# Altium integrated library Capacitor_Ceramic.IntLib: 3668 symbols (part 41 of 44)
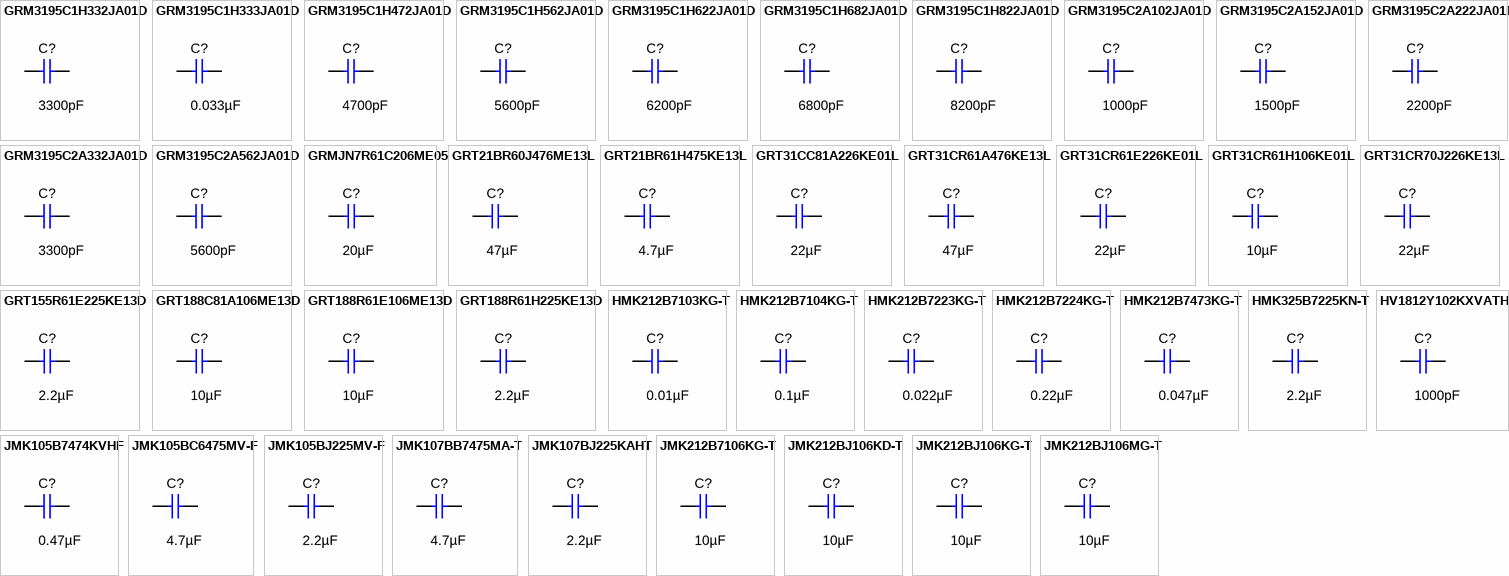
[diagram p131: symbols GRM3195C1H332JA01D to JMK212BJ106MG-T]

## GRM3195C1H682JA01D
designator C?  ValueDisplayed: 6800pF  (hidden comment: GRM3195C1H682JA01D)
CAP, CERM, 6800 pF, 50 V,+/- 5%, C0G/NP0, 1206; Manufacturer: MuRata; Polarized: N; CompType: Capacitor; Value: 6800pF; U/M: EA; Cap_F: 0.0000000068; Tolerance_%: 5; VDC_V: 50; Value2: 50V; TaMin_C: -55; TaMax_C: 125; Cap_Case: 1206; SizeArea_mm2: 5.12; SizeAreaWB_mm2: 10.92; SizeX_mm: 3.2; SizeY_mm: 1.6; SizeZ_mm: 1.35; AEC Category: Q200
signal-integrity model Cap
simulation model Cap
footprint 1206
footprint 1206M
footprint 1206L
pins: 1, 2

## GRM3195C1H822JA01D
designator C?  ValueDisplayed: 8200pF  (hidden comment: GRM3195C1H822JA01D)
CAP, CERM, 8200 pF, 50 V,+/- 5%, C0G/NP0, 1206; Manufacturer: MuRata; Polarized: N; CompType: Capacitor; Value: 8200pF; U/M: EA; Cap_F: 0.0000000082; Tolerance_%: 5; VDC_V: 50; Value2: 50V; TaMin_C: -55; TaMax_C: 125; Cap_Case: 1206; SizeArea_mm2: 5.12; SizeAreaWB_mm2: 10.92; SizeX_mm: 3.2; SizeY_mm: 1.6; SizeZ_mm: 1.35; AEC Category: Q200
signal-integrity model Cap
simulation model Cap
footprint 1206
footprint 1206M
footprint 1206L
pins: 1, 2

## GRM3195C2A102JA01D
designator C?  ValueDisplayed: 1000pF  (hidden comment: GRM3195C2A102JA01D)
CAP, CERM, 1000 pF, 100 V,+/- 5%, C0G/NP0, 1206; Manufacturer: MuRata; Polarized: N; CompType: Capacitor; Value: 1000pF; U/M: EA; Cap_F: 0.000000001; Tolerance_%: 5; VDC_V: 100; Value2: 100V; TaMin_C: -55; TaMax_C: 125; Cap_Case: 1206; SizeArea_mm2: 5.12; SizeAreaWB_mm2: 10.92; SizeX_mm: 3.2; SizeY_mm: 1.6; SizeZ_mm: 1.35; AEC Category: Q200
signal-integrity model Cap
simulation model Cap
footprint 1206
footprint 1206M
footprint 1206L
pins: 1, 2

## GRM3195C2A152JA01D
designator C?  ValueDisplayed: 1500pF  (hidden comment: GRM3195C2A152JA01D)
CAP, CERM, 1500 pF, 100 V,+/- 5%, C0G/NP0, 1206; Manufacturer: MuRata; Polarized: N; CompType: Capacitor; Value: 1500pF; U/M: EA; Cap_F: 0.0000000015; Tolerance_%: 5; VDC_V: 100; Value2: 100V; TaMin_C: -55; TaMax_C: 125; Cap_Case: 1206; SizeArea_mm2: 5.12; SizeAreaWB_mm2: 10.92; SizeX_mm: 3.2; SizeY_mm: 1.6; SizeZ_mm: 1.35; AEC Category: Q200
signal-integrity model Cap
simulation model Cap
footprint 1206
footprint 1206M
footprint 1206L
pins: 1, 2

## GRM3195C2A222JA01D
designator C?  ValueDisplayed: 2200pF  (hidden comment: GRM3195C2A222JA01D)
CAP, CERM, 2200 pF, 100 V,+/- 5%, C0G/NP0, 1206; Manufacturer: MuRata; Polarized: N; CompType: Capacitor; Value: 2200pF; U/M: EA; Cap_F: 0.0000000022; Tolerance_%: 5; VDC_V: 100; Value2: 100V; TaMin_C: -55; TaMax_C: 125; Cap_Case: 1206; SizeArea_mm2: 5.12; SizeAreaWB_mm2: 10.92; SizeX_mm: 3.2; SizeY_mm: 1.6; SizeZ_mm: 1.35; AEC Category: Q200
signal-integrity model Cap
simulation model Cap
footprint 1206
footprint 1206M
footprint 1206L
pins: 1, 2

## GRM3195C2A332JA01D
designator C?  ValueDisplayed: 3300pF  (hidden comment: GRM3195C2A332JA01D)
CAP, CERM, 3300 pF, 100 V,+/- 5%, C0G/NP0, 1206; Manufacturer: MuRata; Polarized: N; CompType: Capacitor; Value: 3300pF; U/M: EA; Cap_F: 0.0000000033; Tolerance_%: 5; ESR_ohm: 0.005; Value1: 0.005 ohm; VDC_V: 100; Value2: 100V; IRMS_A: 0.5; TaMin_C: -55; TaMax_C: 125; Cap_Case: 1206; SizeArea_mm2: 5.12; SizeAreaWB_mm2: 10.92; SizeX_mm: 3.2; SizeY_mm: 1.6; SizeZ_mm: 1.35; AEC Category: Q200
signal-integrity model Cap
simulation model Cap
footprint 1206
footprint 1206M
footprint 1206L
pins: 1, 2

## GRM3195C2A562JA01D
designator C?  ValueDisplayed: 5600pF  (hidden comment: GRM3195C2A562JA01D)
CAP, CERM, 5600 pF, 100 V,+/- 5%, C0G/NP0, 1206; Manufacturer: MuRata; Polarized: N; CompType: Capacitor; Value: 5600pF; U/M: EA; Cap_F: 0.0000000056; Tolerance_%: 5; ESR_ohm: 0.005; Value1: 0.005 ohm; VDC_V: 100; Value2: 100V; IRMS_A: 0.5; TaMin_C: -55; TaMax_C: 125; Cap_Case: 1206; SizeArea_mm2: 5.12; SizeAreaWB_mm2: 10.92; SizeX_mm: 3.2; SizeY_mm: 1.6; SizeZ_mm: 1.35; AEC Category: Q200; Green_Lifecycle: Active; Green_REACh: Passed
signal-integrity model Cap
simulation model Cap
footprint 1206
footprint 1206M
footprint 1206L
pins: 1, 2

## GRMJN7R61C206ME05
designator C?  ValueDisplayed: 20µF  (hidden comment: GRMJN7R61C206ME05)
CAP, CERM, 20 µF, 16 V,+/- 20%, X5R, 0704; Manufacturer: MuRata; Polarized: N; CompType: Capacitor; Value: 20uF; U/M: EA; Cap_F: 2e-005; Tolerance_%: 20; VDC_V: 16; Value2: 16V; TaMin_C: -55; TaMax_C: 85; Cap_Case: 0704; SizeArea_mm2: 1.8; SizeAreaWB_mm2: 5.6; SizeX_mm: 1; SizeZ_mm: 0.8; AEC Category: Q200
signal-integrity model Cap
simulation model Cap
footprint 0704
pins: 1, 2

## GRT21BR60J476ME13L
designator C?  ValueDisplayed: 47µF  (hidden comment: GRT21BR60J476ME13L)
CAP, CERM, 47 µF, 6.3 V,+/- 20%, X5R, AEC-Q200 Grade 3, 0805; Manufacturer: MuRata; Polarized: N; CompType: Capacitor; Value: 47uF; U/M: EA; Cap_F: 0.000047; Tolerance_%: 20; VDC_V: 6.3; Value2: 6.3V; TaMin_C: -55; TaMax_C: 85; Cap_Case: 0805; SizeArea_mm2: 2.5; SizeAreaWB_mm2: 6.75; SizeX_mm: 2; SizeY_mm: 1.25; SizeZ_mm: 1.45; AEC Category: Q200; AEC Qualified: Y; AEC Grade: 3
signal-integrity model Cap
simulation model Cap
footprint 0805_HV
footprint 0805_HV1
footprint 0805
footprint 0805M
footprint 0805L
pins: 1, 2

## GRT21BR61H475KE13L
designator C?  ValueDisplayed: 4.7µF  (hidden comment: GRT21BR61H475KE13L)
CAP, CERM, 4.7 µF, 50 V,+/- 10%, X5R, AEC-Q200 Grade 3, 0805; Manufacturer: MuRata; Polarized: N; CompType: Capacitor; Value: 4.7uF; U/M: EA; Cap_F: 0.0000047; Tolerance_%: 10; VDC_V: 50; Value2: 50V; TaMin_C: -55; TaMax_C: 85; Cap_Case: 0805; SizeArea_mm2: 2.5; SizeAreaWB_mm2: 6.75; SizeX_mm: 2; SizeY_mm: 1.25; SizeZ_mm: 1.45; AEC Category: Q200; AEC Qualified: Y; AEC Grade: 3
signal-integrity model Cap
simulation model Cap
footprint 0805_HV
footprint 0805_HV1
footprint 0805
footprint 0805M
footprint 0805L
pins: 1, 2

## GRT31CC81A226KE01L
designator C?  ValueDisplayed: 22µF  (hidden comment: GRT31CC81A226KE01L)
CAP, CERM, 22 µF, 10 V,+/- 10%, X6S, AEC-Q200 Grade 2, 1206; Manufacturer: MuRata; Polarized: N; CompType: Capacitor; Value: 22uF; U/M: EA; Cap_F: 0.000022; Tolerance_%: 10; Value2: 10V; TaMin_C: -55; TaMax_C: 105; Cap_Case: 1206; SizeArea_mm2: 5.12; SizeAreaWB_mm2: 10.92; SizeX_mm: 3.2; SizeY_mm: 1.6; SizeZ_mm: 1.8; AEC Category: Q200; AEC Qualified: Y; AEC Grade: 2
signal-integrity model Cap
simulation model Cap
footprint 1206_180
footprint 1206_180M
footprint 1206_180L
pins: 1, 2

## GRT31CR61A476KE13L
designator C?  ValueDisplayed: 47µF  (hidden comment: GRT31CR61A476KE13L)
CAP, CERM, 47 µF, 10 V,+/- 10%, X5R, AEC-Q200 Grade 1, 1206; Manufacturer: MuRata; Polarized: N; CompType: Capacitor; Value: 47uF; U/M: EA; Cap_F: 0.000047; Tolerance_%: 10; Value2: 10V; TaMin_C: -55; TaMax_C: 85; Cap_Case: 1206; SizeArea_mm2: 5.12; SizeAreaWB_mm2: 10.92; SizeX_mm: 3.2; SizeY_mm: 1.6; SizeZ_mm: 1.8; AEC Category: Q200; AEC Qualified: Y; AEC Grade: 1
signal-integrity model Cap
simulation model Cap
footprint 1206_180
footprint 1206_180M
footprint 1206_180L
pins: 1, 2

## GRT31CR61E226KE01L
designator C?  ValueDisplayed: 22µF  (hidden comment: GRT31CR61E226KE01L)
CAP, CERM, 22 µF, 25 V,+/- 10%, X5R, AEC-Q200 Grade 3, 1206; Manufacturer: MuRata; Polarized: N; CompType: Capacitor; Value: 22uF; U/M: EA; Cap_F: 0.000022; Tolerance_%: 10; VDC_V: 25; Value2: 25V; TaMin_C: -55; TaMax_C: 85; Cap_Case: 1206; SizeArea_mm2: 5.12; SizeAreaWB_mm2: 10.92; SizeX_mm: 3.2; SizeY_mm: 1.6; SizeZ_mm: 1.8; AEC Category: Q200; AEC Qualified: Y; AEC Grade: 3
signal-integrity model Cap
simulation model Cap
footprint 1206_180
footprint 1206_180M
footprint 1206_180L
pins: 1, 2

## GRT31CR61H106KE01L
designator C?  ValueDisplayed: 10µF  (hidden comment: GRT31CR61H106KE01L)
CAP, CERM, 10 µF, 50 V,+/- 10%, X5R, AEC-Q200 Grade 1, 1206; Manufacturer: MuRata; Polarized: N; CompType: Capacitor; Value: 10uF; U/M: EA; Cap_F: 0.00001; Tolerance_%: 10; VDC_V: 50; Value2: 50V; TaMin_C: -55; TaMax_C: 85; Cap_Case: 1206; SizeArea_mm2: 5.12; SizeAreaWB_mm2: 10.92; SizeX_mm: 3.2; SizeY_mm: 1.6; SizeZ_mm: 1.8; AEC Category: Q200; AEC Qualified: Y; AEC Grade: 1
signal-integrity model Cap
simulation model Cap
footprint 1206_180
footprint 1206_180M
footprint 1206_180L
pins: 1, 2

## GRT31CR70J226KE13L
designator C?  ValueDisplayed: 22µF  (hidden comment: GRT31CR70J226KE13L)
CAP, CERM, 22 µF, 6.3 V,+/- 10%, X7R, AEC-Q200 Grade 1, 1206; Manufacturer: MuRata; Polarized: N; CompType: Capacitor; Value: 22uF; U/M: EA; Cap_F: 0.000022; Tolerance_%: 10; VDC_V: 6.3; Value2: 6.3V; TaMin_C: -55; TaMax_C: 125; Cap_Case: 1206; SizeArea_mm2: 5.12; SizeAreaWB_mm2: 10.92; SizeX_mm: 3.2; SizeY_mm: 1.6; SizeZ_mm: 1.8; AEC Category: Q200; AEC Qualified: Y; AEC Grade: 1
signal-integrity model Cap
simulation model Cap
footprint 1206_180
footprint 1206_180M
footprint 1206_180L
pins: 1, 2

## GRT155R61E225KE13D
designator C?  ValueDisplayed: 2.2µF  (hidden comment: GRT155R61E225KE13D)
CAP, CERM, 2.2 µF, 25 V,+/- 10%, X5R, AEC-Q200 Grade 3, 0402; Manufacturer: MuRata; Polarized: N; CompType: Capacitor; Value: 2.2uF; U/M: EA; Cap_F: 0.0000022; Tolerance_%: 10; VDC_V: 25; Value2: 25V; TaMin_C: -55; TaMax_C: 85; Cap_Case: 0402; SizeArea_mm2: 0.5; SizeAreaWB_mm2: 3; SizeX_mm: 1; SizeZ_mm: 0.6; AEC Category: Q200; AEC Qualified: Y
signal-integrity model Cap
simulation model Cap
footprint 0402
footprint 0402M
footprint 0402L
footprint 0402S
pins: 1, 2

## GRT188C81A106ME13D
designator C?  ValueDisplayed: 10µF  (hidden comment: GRT188C81A106ME13D)
CAP, CERM, 10 µF, 10 V,+/- 20%, X6S, AEC-Q200 Grade 2, 0603; Manufacturer: MuRata; Polarized: N; CompType: Capacitor; Value: 10uF; U/M: EA; Cap_F: 0.00001; Tolerance_%: 20; VDC_V: 10; Value2: 10V; TaMin_C: -55; TaMax_C: 105; Cap_Case: 0603; SizeArea_mm2: 1.28; SizeAreaWB_mm2: 4.68; SizeX_mm: 1.6; SizeY_mm: 0.8; SizeZ_mm: 1; AEC Category: Q200; AEC Qualified: Y; AEC Grade: 2; Green_Lifecycle: Active; Green_REACh: Passed
signal-integrity model Cap
simulation model Cap
footprint 0603
footprint 0603M
footprint 0603L
footprint 0603_HV
footprint 0603S
pins: 1, 2

## GRT188R61E106ME13D
designator C?  ValueDisplayed: 10µF  (hidden comment: GRT188R61E106ME13D)
CAP, CERM, 10 µF, 25 V,+/- 20%, X5R, 0603; Manufacturer: MuRata; Polarized: N; CompType: Capacitor; Value: 10uF; U/M: EA; Cap_F: 0.00001; Tolerance_%: 20; VDC_V: 25; Value2: 25V; TaMin_C: -55; TaMax_C: 85; Cap_Case: 0603; SizeArea_mm2: 1.28; SizeAreaWB_mm2: 4.68; SizeX_mm: 1.6; SizeY_mm: 0.8; SizeZ_mm: 1; AEC Category: Q200
signal-integrity model Cap
simulation model Cap
footprint 0603
footprint 0603M
footprint 0603L
footprint 0603_HV
footprint 0603S
pins: 1, 2

## GRT188R61H225KE13D
designator C?  ValueDisplayed: 2.2µF  (hidden comment: GRT188R61H225KE13D)
CAP, CERM, 2.2 µF, 50 V,+/- 10%, X5R, AEC-Q200 Grade 3, 0603; Manufacturer: MuRata; Polarized: N; CompType: Capacitor; Value: 2.2uF; U/M: EA; Cap_F: 0.0000022; Tolerance_%: 10; VDC_V: 50; Value2: 50V; TaMin_C: -55; TaMax_C: 85; Cap_Case: 0603; SizeArea_mm2: 1.28; SizeAreaWB_mm2: 4.68; SizeX_mm: 1.6; SizeY_mm: 0.8; SizeZ_mm: 1; AEC Category: Q200; AEC Qualified: Y; AEC Grade: 3
signal-integrity model Cap
simulation model Cap
footprint 0603
footprint 0603M
footprint 0603L
footprint 0603_HV
footprint 0603S
pins: 1, 2

## HMK212B7103KG-T
designator C?  ValueDisplayed: 0.01µF  (hidden comment: HMK212B7103KG-T)
CAP, CERM, 0.01 µF, 100 V,+/- 10%, X7R, 0805; Manufacturer: Taiyo Yuden; Polarized: N; CompType: Capacitor; Value: 0.01uF; U/M: EA; Cap_F: 0.00000001; Tolerance_%: 10; VDC_V: 100; Value2: 100V; TaMin_C: -55; TaMax_C: 125; Cap_Case: 0805; SizeArea_mm2: 2.5; SizeAreaWB_mm2: 6.75; SizeX_mm: 2; SizeY_mm: 1.25; SizeZ_mm: 1.45; AEC Category: Q200
signal-integrity model Cap
simulation model Cap
footprint 0805_HV
footprint 0805_HV1
footprint 0805
footprint 0805M
footprint 0805L
pins: 1, 2

## HMK212B7104KG-T
designator C?  ValueDisplayed: 0.1µF  (hidden comment: HMK212B7104KG-T)
CAP, CERM, 0.1 µF, 100 V,+/- 10%, X7R, 0805; Manufacturer: Taiyo Yuden; Polarized: N; CompType: Capacitor; Value: 0.1uF; U/M: EA; Cap_F: 0.0000001; Tolerance_%: 10; VDC_V: 100; Value2: 100V; TaMin_C: -55; TaMax_C: 125; Cap_Case: 0805; SizeArea_mm2: 2.5; SizeAreaWB_mm2: 6.75; SizeX_mm: 2; SizeY_mm: 1.25; SizeZ_mm: 1.45; AEC Category: Q200; Green_Lifecycle: Active; Green_REACh: Passed
signal-integrity model Cap
simulation model Cap
footprint 0805_HV
footprint 0805_HV1
footprint 0805
footprint 0805M
footprint 0805L
pins: 1, 2

## HMK212B7223KG-T
designator C?  ValueDisplayed: 0.022µF  (hidden comment: HMK212B7223KG-T)
CAP, CERM, 0.022 µF, 100 V,+/- 10%, X7R, 0805; Manufacturer: Taiyo Yuden; Polarized: N; CompType: Capacitor; Value: 0.022uF; U/M: EA; Cap_F: 0.000000022; Tolerance_%: 10; VDC_V: 100; Value2: 100V; TaMin_C: -55; TaMax_C: 125; Cap_Case: 0805; SizeArea_mm2: 2.5; SizeAreaWB_mm2: 6.75; SizeX_mm: 2; SizeY_mm: 1.25; SizeZ_mm: 1.45; AEC Category: Q200
signal-integrity model Cap
simulation model Cap
footprint 0805_HV
footprint 0805_HV1
footprint 0805
footprint 0805M
footprint 0805L
pins: 1, 2

## HMK212B7224KG-T
designator C?  ValueDisplayed: 0.22µF  (hidden comment: HMK212B7224KG-T)
CAP, CERM, 0.22 µF, 100 V,+/- 10%, X7R, 0805; Manufacturer: Taiyo Yuden; Polarized: N; CompType: Capacitor; Value: 0.22uF; U/M: EA; Cap_F: 0.00000022; Tolerance_%: 10; VDC_V: 100; Value2: 100V; TaMin_C: -55; TaMax_C: 125; Cap_Case: 0805; SizeArea_mm2: 2.5; SizeAreaWB_mm2: 6.75; SizeX_mm: 2; SizeY_mm: 1.25; SizeZ_mm: 1.45; AEC Category: Q200
signal-integrity model Cap
simulation model Cap
footprint 0805_HV
footprint 0805_HV1
footprint 0805
footprint 0805M
footprint 0805L
pins: 1, 2

## HMK212B7473KG-T
designator C?  ValueDisplayed: 0.047µF  (hidden comment: HMK212B7473KG-T)
CAP, CERM, 0.047 µF, 100 V,+/- 10%, X7R, 0805; Manufacturer: Taiyo Yuden; Polarized: N; CompType: Capacitor; Value: 0.047uF; U/M: EA; Cap_F: 0.000000047; Tolerance_%: 10; VDC_V: 100; Value2: 100V; TaMin_C: -55; TaMax_C: 125; Cap_Case: 0805; SizeArea_mm2: 2.5; SizeAreaWB_mm2: 6.75; SizeX_mm: 2; SizeY_mm: 1.25; SizeZ_mm: 1.45; AEC Category: Q200
signal-integrity model Cap
simulation model Cap
footprint 0805_HV
footprint 0805_HV1
footprint 0805
footprint 0805M
footprint 0805L
pins: 1, 2

## HMK325B7225KN-T
designator C?  ValueDisplayed: 2.2µF  (hidden comment: HMK325B7225KN-T)
CAP, CERM, 2.2 µF, 100 V,+/- 10%, X7R, 1210; Manufacturer: Taiyo Yuden; Polarized: N; CompType: Capacitor; Value: 2.2uF; U/M: EA; Cap_F: 0.0000022; Tolerance_%: 10; VDC_V: 100; Value2: 100V; TaMin_C: -55; TaMax_C: 125; Cap_Case: 1210; SizeArea_mm2: 8; SizeAreaWB_mm2: 14.7; SizeX_mm: 3.2; SizeY_mm: 2.5; SizeZ_mm: 1.35; AEC Category: Q200; Green_Lifecycle: Not Set; Green_REACh: Incomplete
signal-integrity model Cap
simulation model Cap
footprint 1210
footprint 1210M
footprint 1210L
pins: 1, 2

## HV1812Y102KXVATHV
designator C?  ValueDisplayed: 1000pF  (hidden comment: HV1812Y102KXVATHV)
CAP, CERM, 1000 pF, 4000 V,+/- 10%, X7R, 1812; Manufacturer: Vishay-Vitramon; Polarized: N; CompType: Capacitor; Value: 1000pF; U/M: EA; Cap_F: 0.000000001; Tolerance_%: 10; VDC_V: 4000; Value2: 4000V; TaMin_C: -55; TaMax_C: 125; Cap_Case: 1812; SizeArea_mm2: 14.4; SizeAreaWB_mm2: 23.1; SizeX_mm: 4.5; SizeY_mm: 3.2; SizeZ_mm: 2.8; AEC Category: Q200
signal-integrity model Cap
simulation model Cap
footprint 1812_280
footprint 1812_280M
footprint 1812_280L
pins: 1, 2

## JMK105B7474KVHF
designator C?  ValueDisplayed: 0.47µF  (hidden comment: JMK105B7474KVHF)
CAP, CERM, 0.47 µF, 6.3 V,+/- 10%, X7R, 0402; Manufacturer: Taiyo Yuden; Polarized: N; CompType: Capacitor; Value: 0.47uF; U/M: EA; Cap_F: 0.00000047; Tolerance_%: 10; VDC_V: 6.3; Value2: 6.3V; TaMin_C: -55; TaMax_C: 125; Cap_Case: 0402; SizeArea_mm2: 0.5; SizeAreaWB_mm2: 3; SizeX_mm: 1; SizeZ_mm: 0.6; AEC Category: Q200
signal-integrity model Cap
simulation model Cap
footprint 0402
footprint 0402M
footprint 0402L
footprint 0402S
pins: 1, 2

## JMK105BC6475MV-F
designator C?  ValueDisplayed: 4.7µF  (hidden comment: JMK105BC6475MV-F)
CAP, CERM, 4.7 µF, 6.3 V,+/- 20%, X6S, 0402; Manufacturer: Taiyo Yuden; Polarized: N; CompType: Capacitor; Value: 4.7uF; U/M: EA; Cap_F: 0.0000047; Tolerance_%: 20; VDC_V: 6.3; Value2: 6.3V; TaMin_C: -55; TaMax_C: 105; Cap_Case: 0402; SizeArea_mm2: 0.5; SizeAreaWB_mm2: 3; SizeX_mm: 1; SizeZ_mm: 0.6; AEC Category: Q200
signal-integrity model Cap
simulation model Cap
footprint 0402
footprint 0402M
footprint 0402L
footprint 0402S
pins: 1, 2

## JMK105BJ225MV-F
designator C?  ValueDisplayed: 2.2µF  (hidden comment: JMK105BJ225MV-F)
CAP, CERM, 2.2 µF, 6.3 V,+/- 20%, X5R, 0402; Manufacturer: Taiyo Yuden; Polarized: N; CompType: Capacitor; Value: 2.2uF; U/M: EA; Cap_F: 0.0000022; Tolerance_%: 20; ESR_ohm: 0.00152; Value1: 0.00152 ohm; VDC_V: 6.3; Value2: 6.3V; TaMin_C: -55; TaMax_C: 125; Cap_Case: 0402; SizeArea_mm2: 0.5; SizeAreaWB_mm2: 3; SizeX_mm: 1; SizeZ_mm: 0.6; AEC Category: Q200; Green_Lifecycle: Active; Green_REACh: Passed
signal-integrity model Cap
simulation model Cap
footprint 0402
footprint 0402M
footprint 0402L
footprint 0402S
pins: 1, 2

## JMK107BB7475MA-T
designator C?  ValueDisplayed: 4.7µF  (hidden comment: JMK107BB7475MA-T)
CAP, CERM, 4.7 µF, 6.3 V,+/- 10%, X7R, 0603; Manufacturer: Taiyo Yuden; Polarized: N; CompType: Capacitor; Value: 4.7uF; U/M: EA; Cap_F: 0.0000047; Tolerance_%: 10; VDC_V: 6.3; Value2: 6.3V; TaMin_C: -55; TaMax_C: 125; Cap_Case: 0603; SizeArea_mm2: 1.28; SizeAreaWB_mm2: 4.68; SizeX_mm: 1.6; SizeY_mm: 0.8; SizeZ_mm: 1; AEC Category: Q200
signal-integrity model Cap
simulation model Cap
footprint 0603
footprint 0603M
footprint 0603L
footprint 0603_HV
footprint 0603S
pins: 1, 2

## JMK107BJ225KAHT
designator C?  ValueDisplayed: 2.2µF  (hidden comment: JMK107BJ225KAHT)
CAP, CERM, 2.2 µF, 6.3 V,+/- 10%, X5R, 0603; Manufacturer: Taiyo Yuden; Polarized: N; CompType: Capacitor; Value: 2.2uF; U/M: EA; Cap_F: 0.0000022; Tolerance_%: 10; VDC_V: 6.3; Value2: 6.3V; TaMin_C: -55; TaMax_C: 85; Cap_Case: 0603; SizeArea_mm2: 1.28; SizeAreaWB_mm2: 4.68; SizeX_mm: 1.6; SizeY_mm: 0.8; SizeZ_mm: 1; AEC Category: Q200; Green_Lifecycle: Active; Green_REACh: Passed
signal-integrity model Cap
simulation model Cap
footprint 0603
footprint 0603M
footprint 0603L
footprint 0603_HV
footprint 0603S
pins: 1, 2

## JMK212B7106KG-T
designator C?  ValueDisplayed: 10µF  (hidden comment: JMK212B7106KG-T)
CAP, CERM, 10 µF, 6.3 V,+/- 10%, X7R, 0805; Manufacturer: Taiyo Yuden; Polarized: N; CompType: Capacitor; Value: 10uF; U/M: EA; Cap_F: 0.00001; Tolerance_%: 10; VDC_V: 6.3; Value2: 6.3V; TaMin_C: -55; TaMax_C: 125; Cap_Case: 0805; SizeArea_mm2: 2.5; SizeAreaWB_mm2: 6.75; SizeX_mm: 2; SizeY_mm: 1.25; SizeZ_mm: 1.45; AEC Category: Q200; Green_Lifecycle: Not Set; Green_REACh: Incomplete
signal-integrity model Cap
simulation model Cap
footprint 0805_HV
footprint 0805_HV1
footprint 0805
footprint 0805M
footprint 0805L
pins: 1, 2

## JMK212BJ106KD-T
designator C?  ValueDisplayed: 10µF  (hidden comment: JMK212BJ106KD-T)
CAP, CERM, 10 µF, 6.3 V,+/- 10%, X5R, 0805; Manufacturer: Taiyo Yuden; Polarized: N; CompType: Capacitor; Value: 10uF; U/M: EA; Cap_F: 0.00001; Tolerance_%: 10; ESR_ohm: 0.002; Value1: 0.002 ohm; VDC_V: 6.3; Value2: 6.3V; TaMin_C: -55; TaMax_C: 85; Cap_Case: 0805; SizeArea_mm2: 2.5; SizeAreaWB_mm2: 6.75; SizeX_mm: 2; SizeY_mm: 1.25; SizeZ_mm: 1.45; AEC Category: Q200
signal-integrity model Cap
simulation model Cap
footprint 0805_HV
footprint 0805_HV1
footprint 0805
footprint 0805M
footprint 0805L
pins: 1, 2

## JMK212BJ106KG-T
designator C?  ValueDisplayed: 10µF  (hidden comment: JMK212BJ106KG-T)
CAP, CERM, 10 µF, 6.3 V,+/- 10%, X5R, 0805; Manufacturer: Taiyo Yuden; Polarized: N; CompType: Capacitor; Value: 10uF; U/M: EA; Cap_F: 0.00001; Tolerance_%: 10; ESR_ohm: 0.002; Value1: 0.002 ohm; VDC_V: 6.3; Value2: 6.3V; TaMin_C: -55; TaMax_C: 85; Cap_Case: 0805; SizeArea_mm2: 2.5; SizeAreaWB_mm2: 6.75; SizeX_mm: 2; SizeY_mm: 1.25; SizeZ_mm: 1.45; AEC Category: Q200
signal-integrity model Cap
simulation model Cap
footprint 0805_HV
footprint 0805_HV1
footprint 0805
footprint 0805M
footprint 0805L
pins: 1, 2

## JMK212BJ106MG-T
designator C?  ValueDisplayed: 10µF  (hidden comment: JMK212BJ106MG-T)
CAP, CERM, 10 µF, 6.3 V,+/- 20%, X5R, 0805; Manufacturer: Taiyo Yuden; Polarized: N; CompType: Capacitor; Value: 10uF; U/M: EA; Cap_F: 0.00001; Tolerance_%: 20; VDC_V: 6.3; Value2: 6.3V; TaMin_C: -55; TaMax_C: 85; Cap_Case: 0805; SizeArea_mm2: 2.5; SizeAreaWB_mm2: 6.75; SizeX_mm: 2; SizeY_mm: 1.25; SizeZ_mm: 1.45; AEC Category: Q200
signal-integrity model Cap
simulation model Cap
footprint 0805_HV
footprint 0805_HV1
footprint 0805
footprint 0805M
footprint 0805L
pins: 1, 2

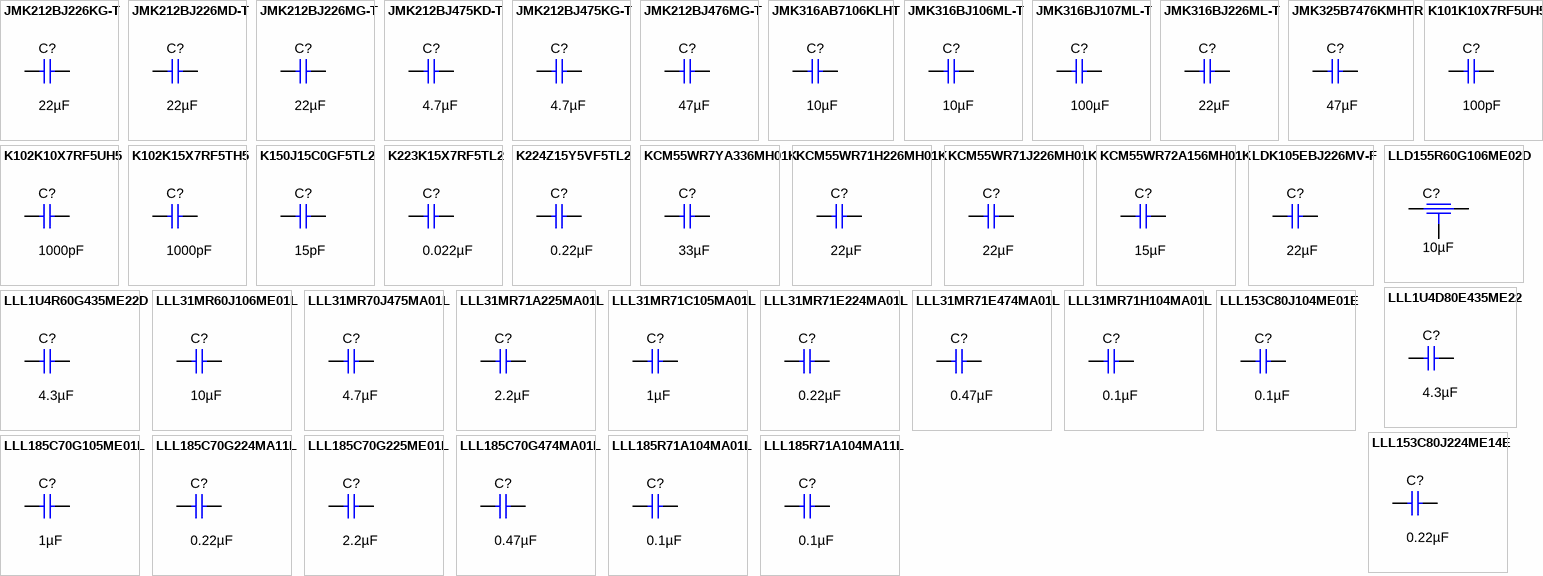
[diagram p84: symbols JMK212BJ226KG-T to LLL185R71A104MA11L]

## JMK212BJ226KG-T
designator C?  ValueDisplayed: 22µF  (hidden comment: JMK212BJ226KG-T)
CAP, CERM, 22 µF, 6.3 V,+/- 10%, X5R, 0805; Manufacturer: Taiyo Yuden; Polarized: N; CompType: Capacitor; Value: 22uF; U/M: EA; Cap_F: 0.000022; Tolerance_%: 10; ESR_ohm: 0.002; Value1: 0.002 ohm; VDC_V: 6.3; Value2: 6.3V; TaMin_C: -55; TaMax_C: 85; Cap_Case: 0805; SizeArea_mm2: 2.5; SizeAreaWB_mm2: 6.75; SizeX_mm: 2; SizeY_mm: 1.25; SizeZ_mm: 1.45; AEC Category: Q200; Green_Lifecycle: Not Set; Green_REACh: Incomplete
signal-integrity model Cap
simulation model Cap
footprint 0805_HV
footprint 0805_HV1
footprint 0805
footprint 0805M
footprint 0805L
pins: 1, 2

## JMK212BJ226MD-T
designator C?  ValueDisplayed: 22µF  (hidden comment: JMK212BJ226MD-T)
CAP, CERM, 22 µF, 6.3 V,+/- 20%, X5R, 0805; Manufacturer: Taiyo Yuden; Polarized: N; CompType: Capacitor; Value: 22uF; U/M: EA; Cap_F: 0.000022; Tolerance_%: 20; VDC_V: 6.3; Value2: 6.3V; TaMin_C: -55; TaMax_C: 85; Cap_Case: 0805; SizeArea_mm2: 2.5; SizeAreaWB_mm2: 6.75; SizeX_mm: 2; SizeY_mm: 1.25; SizeZ_mm: 1.45; AEC Category: Q200
signal-integrity model Cap
simulation model Cap
footprint 0805_HV
footprint 0805_HV1
footprint 0805
footprint 0805M
footprint 0805L
pins: 1, 2

## JMK212BJ226MG-T
designator C?  ValueDisplayed: 22µF  (hidden comment: JMK212BJ226MG-T)
CAP, CERM, 22 µF, 6.3 V,+/- 20%, X5R, 0805; Manufacturer: Taiyo Yuden; Polarized: N; CompType: Capacitor; Value: 22uF; U/M: EA; Cap_F: 0.000022; Tolerance_%: 20; VDC_V: 6.3; Value2: 6.3V; TaMin_C: -55; TaMax_C: 85; Cap_Case: 0805; SizeArea_mm2: 2.5; SizeAreaWB_mm2: 6.75; SizeX_mm: 2; SizeY_mm: 1.25; SizeZ_mm: 1.45; AEC Category: Q200; Green_Lifecycle: Not Set; Green_REACh: Incomplete
signal-integrity model Cap
simulation model Cap
footprint 0805_HV
footprint 0805_HV1
footprint 0805
footprint 0805M
footprint 0805L
pins: 1, 2

## JMK212BJ475KD-T
designator C?  ValueDisplayed: 4.7µF  (hidden comment: JMK212BJ475KD-T)
CAP, CERM, 4.7 µF, 6.3 V,+/- 10%, X5R, 0805; Manufacturer: Taiyo Yuden; Polarized: N; CompType: Capacitor; Value: 4.7uF; U/M: EA; Cap_F: 0.0000047; Tolerance_%: 10; ESR_ohm: 0.004; Value1: 0.004 ohm; VDC_V: 6.3; Value2: 6.3V; TaMin_C: -55; TaMax_C: 85; Cap_Case: 0805; SizeArea_mm2: 2.5; SizeAreaWB_mm2: 6.75; SizeX_mm: 2; SizeY_mm: 1.25; SizeZ_mm: 1.45; AEC Category: Q200
signal-integrity model Cap
simulation model Cap
footprint 0805_HV
footprint 0805_HV1
footprint 0805
footprint 0805M
footprint 0805L
pins: 1, 2

## JMK212BJ475KG-T
designator C?  ValueDisplayed: 4.7µF  (hidden comment: JMK212BJ475KG-T)
CAP, CERM, 4.7 µF, 6.3 V,+/- 10%, X5R, 0805; Manufacturer: Taiyo Yuden; Polarized: N; CompType: Capacitor; Value: 4.7uF; U/M: EA; Cap_F: 0.0000047; Tolerance_%: 10; ESR_ohm: 0.004; Value1: 0.004 ohm; VDC_V: 6.3; Value2: 6.3V; TaMin_C: -55; TaMax_C: 85; Cap_Case: 0805; SizeArea_mm2: 2.5; SizeAreaWB_mm2: 6.75; SizeX_mm: 2; SizeY_mm: 1.25; SizeZ_mm: 1.45; AEC Category: Q200; Green_Lifecycle: Not Set; Green_REACh: Incomplete
signal-integrity model Cap
simulation model Cap
footprint 0805_HV
footprint 0805_HV1
footprint 0805
footprint 0805M
footprint 0805L
pins: 1, 2

## JMK212BJ476MG-T
designator C?  ValueDisplayed: 47µF  (hidden comment: JMK212BJ476MG-T)
CAP, CERM, 47 µF, 6.3 V,+/- 20%, X5R, 0805; Manufacturer: Taiyo Yuden; Polarized: N; CompType: Capacitor; Value: 47uF; U/M: EA; Cap_F: 0.000047; Tolerance_%: 20; VDC_V: 6.3; Value2: 6.3V; TaMin_C: -55; TaMax_C: 85; Cap_Case: 0805; SizeArea_mm2: 2.5; SizeAreaWB_mm2: 6.75; SizeX_mm: 2; SizeY_mm: 1.25; SizeZ_mm: 1.45; AEC Category: Q200; Green_Lifecycle: Not Set; Green_REACh: Incomplete
signal-integrity model Cap
simulation model Cap
footprint 0805_HV
footprint 0805_HV1
footprint 0805
footprint 0805M
footprint 0805L
pins: 1, 2

## JMK316AB7106KLHT
designator C?  ValueDisplayed: 10µF  (hidden comment: JMK316AB7106KLHT)
CAP, CERM, 10 µF, 6.3 V,+/- 10%, X7R, AEC-Q200 Grade 1, 1206; Manufacturer: Taiyo Yuden; Polarized: N; CompType: Capacitor; Value: 10uF; U/M: EA; Cap_F: 0.00001; Tolerance_%: 10; VDC_V: 6.3; Value2: 6.3V; TaMin_C: -55; TaMax_C: 125; Cap_Case: 1206; SizeArea_mm2: 5.12; SizeAreaWB_mm2: 10.92; SizeX_mm: 3.2; SizeY_mm: 1.6; SizeZ_mm: 1.8; AEC Category: Q200; AEC Qualified: Y; AEC Grade: 1
signal-integrity model Cap
simulation model Cap
footprint 1206_180
footprint 1206_180M
footprint 1206_180L
pins: 1, 2

## JMK316BJ106ML-T
designator C?  ValueDisplayed: 10µF  (hidden comment: JMK316BJ106ML-T)
CAP, CERM, 10 µF, 6.3 V,+/- 20%, X5R, 1206; Manufacturer: Taiyo Yuden; Polarized: N; CompType: Capacitor; Value: 10uF; U/M: EA; Cap_F: 0.00001; Tolerance_%: 20; ESR_ohm: 0.008; Value1: 0.008 ohm; VDC_V: 6.3; Value2: 6.3V; TaMin_C: -55; TaMax_C: 125; Cap_Case: 1206; SizeArea_mm2: 5.12; SizeAreaWB_mm2: 10.92; SizeX_mm: 3.2; SizeY_mm: 1.6; SizeZ_mm: 1.35; AEC Category: Q200
signal-integrity model Cap
simulation model Cap
footprint 1206
footprint 1206M
footprint 1206L
pins: 1, 2

## JMK316BJ107ML-T
designator C?  ValueDisplayed: 100µF  (hidden comment: JMK316BJ107ML-T)
CAP, CERM, 100 µF, 6.3 V,+/- 20%, X5R, 1206; Manufacturer: Taiyo Yuden; Polarized: N; CompType: Capacitor; Value: 100uF; U/M: EA; Cap_F: 0.0001; Tolerance_%: 20; VDC_V: 6.3; Value2: 6.3V; TaMin_C: -55; TaMax_C: 85; Cap_Case: 1206; SizeArea_mm2: 5.12; SizeAreaWB_mm2: 10.92; SizeX_mm: 3.2; SizeY_mm: 1.6; SizeZ_mm: 1.35; AEC Category: Q200
signal-integrity model Cap
simulation model Cap
footprint 1206
footprint 1206M
footprint 1206L
pins: 1, 2

## JMK316BJ226ML-T
designator C?  ValueDisplayed: 22µF  (hidden comment: JMK316BJ226ML-T)
CAP, CERM, 22 µF, 6.3 V,+/- 20%, X5R, 1206; Manufacturer: Taiyo Yuden; Polarized: N; CompType: Capacitor; Value: 22uF; U/M: EA; Cap_F: 0.000022; Tolerance_%: 20; ESR_ohm: 0.012; Value1: 0.012 ohm; VDC_V: 6.3; Value2: 6.3V; TaMin_C: -55; TaMax_C: 125; Cap_Case: 1206; SizeArea_mm2: 5.12; SizeAreaWB_mm2: 10.92; SizeX_mm: 3.2; SizeY_mm: 1.6; SizeZ_mm: 1.35; AEC Category: Q200
signal-integrity model Cap
simulation model Cap
footprint 1206
footprint 1206M
footprint 1206L
pins: 1, 2

## JMK325B7476KMHTR
designator C?  ValueDisplayed: 47µF  (hidden comment: JMK325B7476KMHTR)
CAP, CERM, 47 µF, 6.3 V,+/- 10%, X7R, AEC-Q200 Grade 1, 1210; Manufacturer: Taiyo Yuden; Polarized: N; CompType: Capacitor; Value: 47uF; U/M: EA; Cap_F: 0.000047; Tolerance_%: 10; VDC_V: 6.3; Value2: 6.3V; TaMin_C: -55; TaMax_C: 125; Cap_Case: 1210; SizeArea_mm2: 8; SizeAreaWB_mm2: 14.7; SizeX_mm: 3.2; SizeY_mm: 2.5; SizeZ_mm: 2.7; AEC Category: Q200; AEC Qualified: Y; AEC Grade: 1
signal-integrity model Cap
simulation model Cap
footprint 1210_270
footprint 1210_270M
footprint 1210_270L
pins: 1, 2

## K101K10X7RF5UH5
designator C?  ValueDisplayed: 100pF  (hidden comment: K101K10X7RF5UH5)
CAP, CERM, 100 pF, 50 V,+/- 10%, X7R, 3.6x6.2x2.3mm; Manufacturer: Vishay-Bccomponents; Polarized: N; CompType: Capacitor; Value: 100pF; U/M: EA; Cap_F: 0.0000000001; Tolerance_%: 10; VDC_V: 50; Value2: 50V; TaMin_C: -55; TaMax_C: 125; SizeArea_mm2: 8.28; SizeAreaWB_mm2: 15.18; SizeX_mm: 3.6; SizeY_mm: 2.3; SizeZ_mm: 6.2; AEC Category: Q200
signal-integrity model Cap
simulation model Cap
footprint K_10_H5
pins: 1, 2

## K102K10X7RF5UH5
designator C?  ValueDisplayed: 1000pF  (hidden comment: K102K10X7RF5UH5)
CAP, CERM, 1000 pF, 50 V,+/- 10%, X7R, 3.6x2.3mm; Manufacturer: Vishay-Bccomponents; Polarized: N; CompType: Capacitor; Value: 1000pF; U/M: EA; Cap_F: 0.000000001; Tolerance_%: 10; VDC_V: 50; Value2: 50V; TaMin_C: -55; TaMax_C: 125; Cap_Case: 3.6x2.3x6.2mm; SizeArea_mm2: 8.28; SizeAreaWB_mm2: 15.18; SizeX_mm: 3.6; SizeY_mm: 2.3; SizeZ_mm: 6.2; AEC Category: Q200
signal-integrity model Cap
simulation model Cap
footprint K10_360x230x620
pins: 1, 2

## K102K15X7RF5TH5
designator C?  ValueDisplayed: 1000pF  (hidden comment: K102K15X7RF5TH5)
CAP, CERM, 1000 pF, 50 V,+/- 10%, X7R, 4.0x6.6x2.6mm; Manufacturer: Vishay-Bccomponents; Polarized: N; CompType: Capacitor; Value: 1000pF; U/M: EA; Cap_F: 0.000000001; Tolerance_%: 10; VDC_V: 50; Value2: 50V; TaMin_C: -55; TaMax_C: 125; Cap_Case: 4x6.6x2.6mm; SizeAreaWB_mm2: 17.5; SizeX_mm: 4; SizeY_mm: 2.5; SizeZ_mm: 6.6; AEC Category: Q200
signal-integrity model Cap
simulation model Cap
footprint K_15_H5
pins: 1, 2

## K150J15C0GF5TL2
designator C?  ValueDisplayed: 15pF  (hidden comment: K150J15C0GF5TL2)
CAP, CERM, 15 pF, 50 V,+/- 5%, C0G/NP0, 4.0x5.6x2.6mm; Manufacturer: Vishay-Bccomponents; Polarized: N; CompType: Capacitor; Value: 15pF; U/M: EA; Cap_F: 0.000000000015; Tolerance_%: 5; VDC_V: 50; Value2: 50V; TaMin_C: -55; TaMax_C: 125; Cap_Case: K_15_L2; SizeArea_mm2: 10; SizeAreaWB_mm2: 17.5; SizeX_mm: 4; SizeY_mm: 2.5; SizeZ_mm: 5.6; AEC Category: Q200
signal-integrity model Cap
simulation model Cap
footprint K_15_L2
pins: 1, 2

## K223K15X7RF5TL2
designator C?  ValueDisplayed: 0.022µF  (hidden comment: K223K15X7RF5TL2)
CAP, CERM, 0.022 µF, 50 V,+/- 10%, X7R, 4.0x5.6x2.6mm; Manufacturer: Vishay-Bccomponents; Polarized: N; CompType: Capacitor; Value: 0.022uF; U/M: EA; Cap_F: 0.000000022; Tolerance_%: 10; VDC_V: 50; Value2: 50V; TaMin_C: -55; TaMax_C: 125; Cap_Case: K_15_L2; SizeAreaWB_mm2: 17.5; SizeX_mm: 4; SizeY_mm: 2.5; SizeZ_mm: 5.6; AEC Category: Q200
signal-integrity model Cap
simulation model Cap
footprint K_15_L2
pins: 1, 2

## K224Z15Y5VF5TL2
designator C?  ValueDisplayed: 0.22µF  (hidden comment: K224Z15Y5VF5TL2)
CAP, CERM, 0.22 µF, 50 V,+/- 80%, Y5V, 4.0x5.6x2.6mm; Manufacturer: Vishay-Bccomponents; Polarized: N; CompType: Capacitor; Value: 0.22uF; U/M: EA; Cap_F: 0.00000022; Tolerance_%: 80; VDC_V: 50; Value2: 50V; TaMin_C: -30; TaMax_C: 85; Cap_Case: K_15_L2; SizeArea_mm2: 10; SizeAreaWB_mm2: 17.5; SizeX_mm: 4; SizeY_mm: 2.5; SizeZ_mm: 5.6; AEC Category: Q200
signal-integrity model Cap
simulation model Cap
footprint K_15_L2
pins: 1, 2

## KCM55WR7YA336MH01K
designator C?  ValueDisplayed: 33µF  (hidden comment: KCM55WR7YA336MH01K)
CAP, CERM, 33 µF, 35 V,+/- 20%, X7R, Stacked 2220; Manufacturer: MuRata; Polarized: N; CompType: Capacitor; Value: 33uF; U/M: EA; Cap_F: 0.000033; Tolerance_%: 20; VDC_V: 35; Value2: 35V; TaMin_C: -55; TaMax_C: 125; Cap_Case: 2220; SizeArea_mm2: 32.33; SizeAreaWB_mm2: 59.13; SizeX_mm: 6.1; SizeY_mm: 5.3; SizeZ_mm: 6.7; AEC Category: Q200
signal-integrity model Cap
simulation model Cap
footprint KCM55W
pins: 1, 2

## KCM55WR71H226MH01K
designator C?  ValueDisplayed: 22µF  (hidden comment: KCM55WR71H226MH01K)
CAP, CERM, 22 µF, 50 V,+/- 20%, X7R, Stacked 2220; Manufacturer: MuRata; Polarized: N; CompType: Capacitor; Value: 22uF; U/M: EA; Cap_F: 0.000022; Tolerance_%: 20; VDC_V: 50; Value2: 50V; TaMin_C: -55; TaMax_C: 125; Cap_Case: 2220; SizeArea_mm2: 32.33; SizeAreaWB_mm2: 59.13; SizeX_mm: 6.1; SizeY_mm: 5.3; SizeZ_mm: 6.7; AEC Category: Q200
signal-integrity model Cap
simulation model Cap
footprint KCM55W
pins: 1, 2

## KCM55WR71J226MH01K
designator C?  ValueDisplayed: 22µF  (hidden comment: KCM55WR71J226MH01K)
CAP, CERM, 22 µF, 63 V,+/- 20%, X7R, Stacked 2220; Manufacturer: MuRata; Polarized: N; CompType: Capacitor; Value: 22uF; U/M: EA; Cap_F: 0.000022; Tolerance_%: 20; VDC_V: 63; Value2: 63V; TaMin_C: -55; TaMax_C: 125; Cap_Case: 2220; SizeArea_mm2: 32.33; SizeAreaWB_mm2: 59.13; SizeX_mm: 6.1; SizeY_mm: 5.3; SizeZ_mm: 6.7; AEC Category: Q200
signal-integrity model Cap
simulation model Cap
footprint KCM55W
pins: 1, 2

## KCM55WR72A156MH01K
designator C?  ValueDisplayed: 15µF  (hidden comment: KCM55WR72A156MH01K)
CAP, CERM, 15 µF, 100 V,+/- 20%, X7R, Stacked 2220; Manufacturer: MuRata; Polarized: N; CompType: Capacitor; Value: 15uF; U/M: EA; Cap_F: 0.000015; Tolerance_%: 20; VDC_V: 100; Value2: 100V; TaMin_C: -55; TaMax_C: 125; Cap_Case: 2220; SizeArea_mm2: 32.33; SizeAreaWB_mm2: 59.13; SizeX_mm: 6.1; SizeY_mm: 5.3; SizeZ_mm: 6.7; AEC Category: Q200
signal-integrity model Cap
simulation model Cap
footprint KCM55W
pins: 1, 2

## LDK105EBJ226MV-F
designator C?  ValueDisplayed: 22µF  (hidden comment: LDK105EBJ226MV-F)
CAP, CERM, 22 µF, 10 V,+/- 20%, X5R, 0402; Manufacturer: Taiyo Yuden; Polarized: N; CompType: Capacitor; Value: 22uF; U/M: EA; Cap_F: 0.000022; Tolerance_%: 20; VDC_V: 10; Value2: 10V; TaMin_C: -55; TaMax_C: 105; Cap_Case: 0402; SizeArea_mm2: 0.5; SizeAreaWB_mm2: 3; SizeX_mm: 1; SizeZ_mm: 0.8; AEC Category: Q200
signal-integrity model Cap
simulation model Cap
footprint 0402_080
footprint 0402_080S
pins: 1, 2

## LLD155R60G106ME02D
designator C?  ValueDisplayed: 10µF  (hidden comment: LLD155R60G106ME02D)
CAP, CERM, 10 µF, 4 V,+/- 20%, X5R, 0402; Manufacturer: MuRata; SymbolCreator: a0411947; CompType: Capacitor; U/M: EA; Cap_F: 0.00001; Value: 10uF; Tolerance_%: 20; VDC_V: 4; Value2: 4V; TaMin_C: -55; TaMax_C: 85; Polarized: N; Cap_Case: 0402; SizeArea_mm2: 0.5; SizeAreaWB_mm2: 3; SizeX_mm: 1; SizeZ_mm: 0.7; AEC Category: Q200
footprint LLD155
pins: 1, 2, 3

## LLL1U4D80E435ME22
designator C?  ValueDisplayed: 4.3µF  (hidden comment: LLL1U4D80E435ME22)
CAP, CERM, 4.3 µF, 2.5 V,+/- 20%, X6T, SMD, 2-Leads, Body 0.6x1mm, Height 0.45mm; Manufacturer: MuRata; Polarized: N; CompType: Capacitor; Value: 4.3uF; U/M: EA; Cap_F: 4.3e-006; Tolerance_%: 20; ESR_ohm: 0.0029; Value1: 0.0029 ohm; VDC_V: 2.5; Value2: 2.5V; TaMin_C: -55; TaMax_C: 105; Cap_Case: 02404; SizeArea_mm2: 0.6; SizeAreaWB_mm2: 3.2; SizeY_mm: 1; SizeZ_mm: 0.45; AEC Category: Q200
signal-integrity model Cap
simulation model Cap
footprint 02404
pins: 1, 2

## LLL1U4R60G435ME22D
designator C?  ValueDisplayed: 4.3µF  (hidden comment: LLL1U4R60G435ME22D)
CAP, CERM, 4.3 µF, 4 V,+/- 20%, X5R, SMD, 2-Leads, Body 0.6x1mm, Height 0.45mm; Manufacturer: MuRata; Polarized: N; CompType: Capacitor; Value: 4.3uF; U/M: EA; Cap_F: 4.3e-006; Tolerance_%: 20; VDC_V: 4; Value2: 4V; TaMin_C: -55; TaMax_C: 85; Cap_Case: 02404; SizeArea_mm2: 0.6; SizeAreaWB_mm2: 3.2; SizeY_mm: 1; SizeZ_mm: 0.45; AEC Category: Q200
signal-integrity model Cap
simulation model Cap
footprint 02404
pins: 1, 2

## LLL31MR60J106ME01L
designator C?  ValueDisplayed: 10µF  (hidden comment: LLL31MR60J106ME01L)
CAP, CERM, 10 µF, 6.3 V,+/- 20%, X5R, 0612; Manufacturer: MuRata; Polarized: N; CompType: Capacitor; Value: 10uF; U/M: EA; Cap_F: 0.00001; Tolerance_%: 20; VDC_V: 6.3; Value2: 6.3V; TaMin_C: -55; TaMax_C: 85; Cap_Case: 0612; SizeArea_mm2: 5.12; SizeAreaWB_mm2: 10.92; SizeX_mm: 1.6; SizeY_mm: 3.2; SizeZ_mm: 0.85; AEC Category: Q200
signal-integrity model Cap
simulation model Cap
footprint 0612
pins: 1, 2

## LLL31MR70J475MA01L
designator C?  ValueDisplayed: 4.7µF  (hidden comment: LLL31MR70J475MA01L)
CAP, CERM, 4.7 µF, 6.3 V,+/- 20%, X7R, 0612; Manufacturer: MuRata; Polarized: N; CompType: Capacitor; Value: 4.7uF; U/M: EA; Cap_F: 0.0000047; Tolerance_%: 20; VDC_V: 6.3; Value2: 6.3V; TaMin_C: -55; TaMax_C: 125; Cap_Case: 0612; SizeArea_mm2: 5.12; SizeAreaWB_mm2: 10.92; SizeX_mm: 1.6; SizeY_mm: 3.2; SizeZ_mm: 0.85; AEC Category: Q200
signal-integrity model Cap
simulation model Cap
footprint 0612
pins: 1, 2

## LLL31MR71A225MA01L
designator C?  ValueDisplayed: 2.2µF  (hidden comment: LLL31MR71A225MA01L)
CAP, CERM, 2.2 µF, 10 V,+/- 20%, X7R, 0612; Manufacturer: MuRata; Polarized: N; CompType: Capacitor; Value: 2.2uF; U/M: EA; Cap_F: 0.0000022; Tolerance_%: 20; VDC_V: 10; Value2: 10V; TaMin_C: -55; TaMax_C: 125; Cap_Case: 0612; SizeArea_mm2: 5.12; SizeAreaWB_mm2: 10.92; SizeX_mm: 1.6; SizeY_mm: 3.2; SizeZ_mm: 0.85; AEC Category: Q200
signal-integrity model Cap
simulation model Cap
footprint 0612
pins: 1, 2

## LLL31MR71C105MA01L
designator C?  ValueDisplayed: 1µF  (hidden comment: LLL31MR71C105MA01L)
CAP, CERM, 1 µF, 16 V,+/- 20%, X7R, 0612; Manufacturer: MuRata; Polarized: N; CompType: Capacitor; Value: 1uF; U/M: EA; Cap_F: 0.000001; Tolerance_%: 20; VDC_V: 16; Value2: 16V; TaMin_C: -55; TaMax_C: 125; Cap_Case: 0612; SizeArea_mm2: 5.12; SizeAreaWB_mm2: 10.92; SizeX_mm: 1.6; SizeY_mm: 3.2; SizeZ_mm: 0.85; AEC Category: Q200
signal-integrity model Cap
simulation model Cap
footprint 0612
pins: 1, 2

## LLL31MR71E224MA01L
designator C?  ValueDisplayed: 0.22µF  (hidden comment: LLL31MR71E224MA01L)
CAP, CERM, 0.22 µF, 25 V,+/- 20%, X7R, 0612; Manufacturer: MuRata; Polarized: N; CompType: Capacitor; Value: 0.22uF; U/M: EA; Cap_F: 0.00000022; Tolerance_%: 20; VDC_V: 25; Value2: 25V; TaMin_C: -55; TaMax_C: 125; Cap_Case: 0612; SizeArea_mm2: 5.12; SizeAreaWB_mm2: 10.92; SizeX_mm: 1.6; SizeY_mm: 3.2; SizeZ_mm: 0.85; AEC Category: Q200
signal-integrity model Cap
simulation model Cap
footprint 0612
pins: 1, 2

## LLL31MR71E474MA01L
designator C?  ValueDisplayed: 0.47µF  (hidden comment: LLL31MR71E474MA01L)
CAP, CERM, 0.47 µF, 25 V,+/- 20%, X7R, 0612; Manufacturer: MuRata; Polarized: N; CompType: Capacitor; Value: 0.47uF; U/M: EA; Cap_F: 0.00000047; Tolerance_%: 20; VDC_V: 25; Value2: 25V; TaMin_C: -55; TaMax_C: 125; Cap_Case: 0612; SizeArea_mm2: 5.12; SizeAreaWB_mm2: 10.92; SizeX_mm: 1.6; SizeY_mm: 3.2; SizeZ_mm: 0.85; AEC Category: Q200
signal-integrity model Cap
simulation model Cap
footprint 0612
pins: 1, 2

## LLL31MR71H104MA01L
designator C?  ValueDisplayed: 0.1µF  (hidden comment: LLL31MR71H104MA01L)
CAP, CERM, 0.1 µF, 50 V,+/- 20%, X7R, 0612; Manufacturer: MuRata; Polarized: N; CompType: Capacitor; Value: 0.1uF; U/M: EA; Cap_F: 0.0000001; Tolerance_%: 20; VDC_V: 50; Value2: 50V; TaMin_C: -55; TaMax_C: 125; Cap_Case: 0612; SizeArea_mm2: 5.12; SizeAreaWB_mm2: 10.92; SizeX_mm: 1.6; SizeY_mm: 3.2; SizeZ_mm: 0.85; AEC Category: Q200
signal-integrity model Cap
simulation model Cap
footprint 0612
pins: 1, 2

## LLL153C80J104ME01E
designator C?  ValueDisplayed: 0.1µF  (hidden comment: LLL153C80J104ME01E)
CAP, CERM, 0.1 µF, 6.3 V,+/- 20%, X6S, SMD, Body 1x0.52mm; Manufacturer: MuRata; Polarized: N; CompType: Capacitor; Value: 0.1uF; U/M: EA; Cap_F: 0.0000001; Tolerance_%: 20; VDC_V: 6.3; Value2: 6.3V; TaMin_C: -55; TaMax_C: 105; Cap_Case: 0204; SizeArea_mm2: 0.5; SizeAreaWB_mm2: 3; SizeY_mm: 1; SizeZ_mm: 0.35; AEC Category: Q200
signal-integrity model Cap
simulation model Cap
footprint 0204
pins: 1, 2

## LLL153C80J224ME14E
designator C?  ValueDisplayed: 0.22µF  (hidden comment: LLL153C80J224ME14E)
CAP, CERM, 0.22 µF, 6.3 V,+/- 20%, X6S, SMD, Body 1x0.52mm; Manufacturer: MuRata; Polarized: N; CompType: Capacitor; Value: 0.22uF; U/M: EA; Cap_F: 0.00000022; Tolerance_%: 20; VDC_V: 6.3; Value2: 6.3V; TaMin_C: -55; TaMax_C: 105; Cap_Case: 0204; SizeArea_mm2: 0.5; SizeAreaWB_mm2: 3; SizeY_mm: 1; SizeZ_mm: 0.35; AEC Category: Q200
signal-integrity model Cap
simulation model Cap
footprint 0204
pins: 1, 2

## LLL185C70G105ME01L
designator C?  ValueDisplayed: 1µF  (hidden comment: LLL185C70G105ME01L)
CAP, CERM, 1 µF, 4 V,+/- 20%, X7S, 0306; Manufacturer: MuRata; Polarized: N; CompType: Capacitor; Value: 1uF; U/M: EA; Cap_F: 0.000001; Tolerance_%: 20; VDC_V: 4; Value2: 4V; TaMin_C: -55; TaMax_C: 125; Cap_Case: 0306; SizeArea_mm2: 1.28; SizeAreaWB_mm2: 4.68; SizeX_mm: 0.8; SizeY_mm: 1.6; SizeZ_mm: 0.6; AEC Category: Q200
signal-integrity model Cap
simulation model Cap
footprint 0306
pins: 1, 2

## LLL185C70G224MA11L
designator C?  ValueDisplayed: 0.22µF  (hidden comment: LLL185C70G224MA11L)
CAP, CERM, 0.22 µF, 4 V,+/- 20%, X7S, 0306; Manufacturer: MuRata; Polarized: N; CompType: Capacitor; Value: 0.22uF; U/M: EA; Cap_F: 0.00000022; Tolerance_%: 20; VDC_V: 4; Value2: 4V; TaMin_C: -55; TaMax_C: 125; Cap_Case: 0306; SizeArea_mm2: 1.28; SizeAreaWB_mm2: 4.68; SizeX_mm: 0.8; SizeY_mm: 1.6; SizeZ_mm: 0.6; AEC Category: Q200
signal-integrity model Cap
simulation model Cap
footprint 0306
pins: 1, 2

## LLL185C70G225ME01L
designator C?  ValueDisplayed: 2.2µF  (hidden comment: LLL185C70G225ME01L)
CAP, CERM, 2.2 µF, 4 V,+/- 20%, X7S, 0306; Manufacturer: MuRata; Polarized: N; CompType: Capacitor; Value: 2.2uF; U/M: EA; Cap_F: 0.0000022; Tolerance_%: 20; VDC_V: 4; Value2: 4V; TaMin_C: -55; TaMax_C: 125; Cap_Case: 0306; SizeArea_mm2: 1.28; SizeAreaWB_mm2: 4.68; SizeX_mm: 0.8; SizeY_mm: 1.6; SizeZ_mm: 0.6; AEC Category: Q200
signal-integrity model Cap
simulation model Cap
footprint 0306
pins: 1, 2

## LLL185C70G474MA01L
designator C?  ValueDisplayed: 0.47µF  (hidden comment: LLL185C70G474MA01L)
CAP, CERM, 0.47 µF, 4 V,+/- 20%, X7S, 0306; Manufacturer: MuRata; Polarized: N; CompType: Capacitor; Value: 0.47uF; U/M: EA; Cap_F: 0.00000047; Tolerance_%: 20; VDC_V: 4; Value2: 4V; TaMin_C: -55; TaMax_C: 125; Cap_Case: 0306; SizeArea_mm2: 1.28; SizeAreaWB_mm2: 4.68; SizeX_mm: 0.8; SizeY_mm: 1.6; SizeZ_mm: 0.6; AEC Category: Q200
signal-integrity model Cap
simulation model Cap
footprint 0306
pins: 1, 2

## LLL185R71A104MA01L
designator C?  ValueDisplayed: 0.1µF  (hidden comment: LLL185R71A104MA01L)
CAP, CERM, 0.1 µF, 10 V,+/- 20%, X7R, 0306; Manufacturer: MuRata; Polarized: N; CompType: Capacitor; Value: 0.1uF; U/M: EA; Cap_F: 0.0000001; Tolerance_%: 20; VDC_V: 10; Value2: 10V; TaMin_C: -55; TaMax_C: 125; Cap_Case: 0306; SizeArea_mm2: 1.28; SizeAreaWB_mm2: 4.68; SizeX_mm: 0.8; SizeY_mm: 1.6; SizeZ_mm: 0.6; AEC Category: Q200
signal-integrity model Cap
simulation model Cap
footprint 0306
pins: 1, 2

## LLL185R71A104MA11L
designator C?  ValueDisplayed: 0.1µF  (hidden comment: LLL185R71A104MA11L)
CAP, CERM, 0.1 µF, 10 V,+/- 20%, X7R, 0306; Manufacturer: MuRata; Polarized: N; CompType: Capacitor; Value: 0.1uF; U/M: EA; Cap_F: 0.0000001; Tolerance_%: 20; VDC_V: 10; Value2: 10V; TaMin_C: -55; TaMax_C: 125; Cap_Case: 0306; SizeArea_mm2: 1.28; SizeAreaWB_mm2: 4.68; SizeX_mm: 0.8; SizeY_mm: 1.6; SizeZ_mm: 0.6; AEC Category: Q200
signal-integrity model Cap
simulation model Cap
footprint 0306
pins: 1, 2

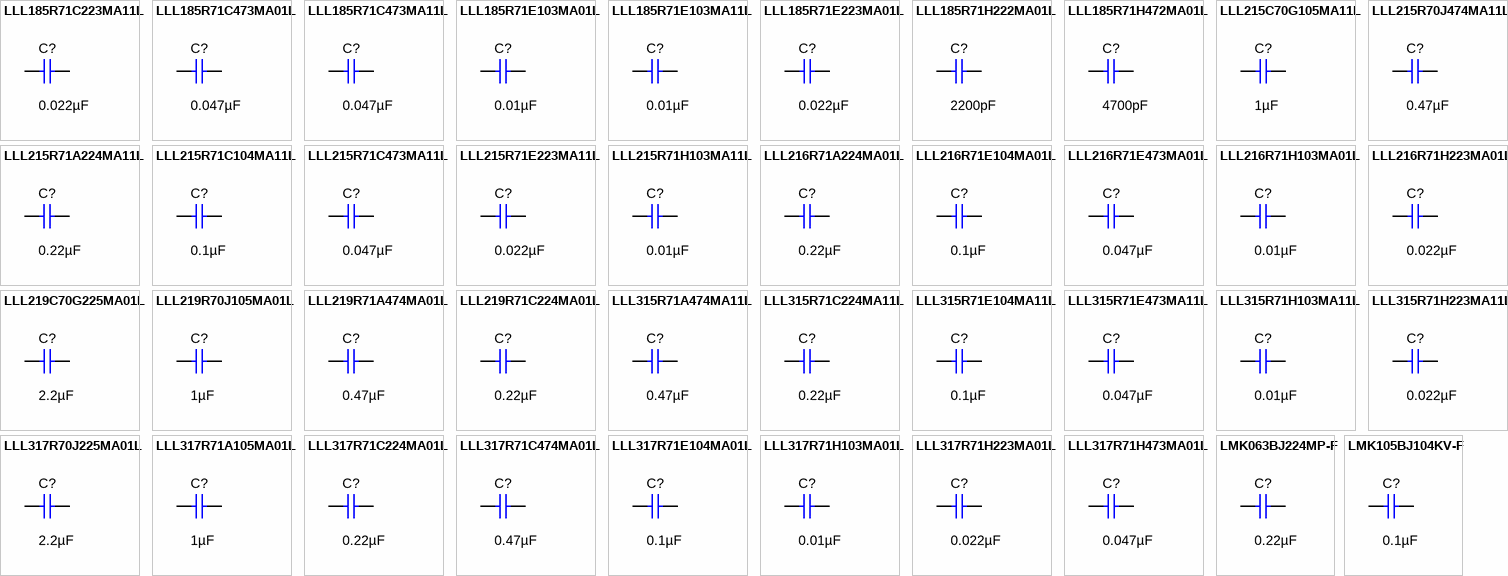
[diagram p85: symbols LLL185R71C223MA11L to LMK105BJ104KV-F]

## LLL185R71C223MA11L
designator C?  ValueDisplayed: 0.022µF  (hidden comment: LLL185R71C223MA11L)
CAP, CERM, 0.022 µF, 16 V,+/- 20%, X7R, 0306; Manufacturer: MuRata; Polarized: N; CompType: Capacitor; Value: 0.022uF; U/M: EA; Cap_F: 0.000000022; Tolerance_%: 20; VDC_V: 16; Value2: 16V; TaMin_C: -55; TaMax_C: 125; Cap_Case: 0306; SizeArea_mm2: 1.28; SizeAreaWB_mm2: 4.68; SizeX_mm: 0.8; SizeY_mm: 1.6; SizeZ_mm: 0.6; AEC Category: Q200
signal-integrity model Cap
simulation model Cap
footprint 0306
pins: 1, 2

## LLL185R71C473MA01L
designator C?  ValueDisplayed: 0.047µF  (hidden comment: LLL185R71C473MA01L)
CAP, CERM, 0.047 µF, 16 V,+/- 20%, X7R, 0306; Manufacturer: MuRata; Polarized: N; CompType: Capacitor; Value: 0.047uF; U/M: EA; Cap_F: 0.000000047; Tolerance_%: 20; VDC_V: 16; Value2: 16V; TaMin_C: -55; TaMax_C: 125; Cap_Case: 0306; SizeArea_mm2: 1.28; SizeAreaWB_mm2: 4.68; SizeX_mm: 0.8; SizeY_mm: 1.6; SizeZ_mm: 0.6; AEC Category: Q200
signal-integrity model Cap
simulation model Cap
footprint 0306
pins: 1, 2

## LLL185R71C473MA11L
designator C?  ValueDisplayed: 0.047µF  (hidden comment: LLL185R71C473MA11L)
CAP, CERM, 0.047 µF, 16 V,+/- 20%, X7R, 0306; Manufacturer: MuRata; Polarized: N; CompType: Capacitor; Value: 0.047uF; U/M: EA; Cap_F: 0.000000047; Tolerance_%: 20; VDC_V: 16; Value2: 16V; TaMin_C: -55; TaMax_C: 125; Cap_Case: 0306; SizeArea_mm2: 1.28; SizeAreaWB_mm2: 4.68; SizeX_mm: 0.8; SizeY_mm: 1.6; SizeZ_mm: 0.6; AEC Category: Q200
signal-integrity model Cap
simulation model Cap
footprint 0306
pins: 1, 2

## LLL185R71E103MA01L
designator C?  ValueDisplayed: 0.01µF  (hidden comment: LLL185R71E103MA01L)
CAP, CERM, 0.01 µF, 25 V,+/- 20%, X7R, 0306; Manufacturer: MuRata; Polarized: N; CompType: Capacitor; Value: 0.01uF; U/M: EA; Cap_F: 0.00000001; Tolerance_%: 20; VDC_V: 25; Value2: 25V; TaMin_C: -55; TaMax_C: 125; Cap_Case: 0306; SizeArea_mm2: 1.28; SizeAreaWB_mm2: 4.68; SizeX_mm: 0.8; SizeY_mm: 1.6; SizeZ_mm: 0.6; AEC Category: Q200; Green_Lifecycle: Not Set; Green_REACh: Incomplete
signal-integrity model Cap
simulation model Cap
footprint 0306
pins: 1, 2

## LLL185R71E103MA11L
designator C?  ValueDisplayed: 0.01µF  (hidden comment: LLL185R71E103MA11L)
CAP, CERM, 0.01 µF, 25 V,+/- 20%, X7R, 0306; Manufacturer: MuRata; Polarized: N; CompType: Capacitor; Value: 0.01uF; U/M: EA; Cap_F: 0.00000001; Tolerance_%: 20; VDC_V: 25; Value2: 25V; TaMin_C: -55; TaMax_C: 125; Cap_Case: 0306; SizeArea_mm2: 1.28; SizeAreaWB_mm2: 4.68; SizeX_mm: 0.8; SizeY_mm: 1.6; SizeZ_mm: 0.6; AEC Category: Q200
signal-integrity model Cap
simulation model Cap
footprint 0306
pins: 1, 2

## LLL185R71E223MA01L
designator C?  ValueDisplayed: 0.022µF  (hidden comment: LLL185R71E223MA01L)
CAP, CERM, 0.022 µF, 25 V,+/- 20%, X7R, 0306; Manufacturer: MuRata; Polarized: N; CompType: Capacitor; Value: 0.022uF; U/M: EA; Cap_F: 0.000000022; Tolerance_%: 20; VDC_V: 25; Value2: 25V; TaMin_C: -55; TaMax_C: 125; Cap_Case: 0306; SizeArea_mm2: 1.28; SizeAreaWB_mm2: 4.68; SizeX_mm: 0.8; SizeY_mm: 1.6; SizeZ_mm: 0.6; AEC Category: Q200
signal-integrity model Cap
simulation model Cap
footprint 0306
pins: 1, 2

## LLL185R71H222MA01L
designator C?  ValueDisplayed: 2200pF  (hidden comment: LLL185R71H222MA01L)
CAP, CERM, 2200 pF, 50 V,+/- 20%, X7R, 0306; Manufacturer: MuRata; Polarized: N; CompType: Capacitor; Value: 2200pF; U/M: EA; Cap_F: 0.0000000022; Tolerance_%: 20; VDC_V: 50; Value2: 50V; TaMin_C: -55; TaMax_C: 125; Cap_Case: 0306; SizeArea_mm2: 1.28; SizeAreaWB_mm2: 4.68; SizeX_mm: 0.8; SizeY_mm: 1.6; SizeZ_mm: 0.6; AEC Category: Q200; Green_Lifecycle: Not Set; Green_REACh: Incomplete
signal-integrity model Cap
simulation model Cap
footprint 0306
pins: 1, 2

## LLL185R71H472MA01L
designator C?  ValueDisplayed: 4700pF  (hidden comment: LLL185R71H472MA01L)
CAP, CERM, 4700 pF, 50 V,+/- 20%, X7R, 0306; Manufacturer: MuRata; Polarized: N; CompType: Capacitor; Value: 4700pF; U/M: EA; Cap_F: 0.0000000047; Tolerance_%: 20; VDC_V: 50; Value2: 50V; TaMin_C: -55; TaMax_C: 125; Cap_Case: 0306; SizeArea_mm2: 1.28; SizeAreaWB_mm2: 4.68; SizeX_mm: 0.8; SizeY_mm: 1.6; SizeZ_mm: 0.6; AEC Category: Q200
signal-integrity model Cap
simulation model Cap
footprint 0306
pins: 1, 2

## LLL215C70G105MA11L
designator C?  ValueDisplayed: 1µF  (hidden comment: LLL215C70G105MA11L)
CAP, CERM, 1 µF, 4 V,+/- 20%, X7S, 0508; Manufacturer: MuRata; Polarized: N; CompType: Capacitor; Value: 1uF; U/M: EA; Cap_F: 0.000001; Tolerance_%: 20; VDC_V: 4; Value2: 4V; TaMin_C: -55; TaMax_C: 125; Cap_Case: 0508; SizeArea_mm2: 2.5; SizeAreaWB_mm2: 6.75; SizeX_mm: 1.25; SizeY_mm: 2; SizeZ_mm: 1; AEC Category: Q200
signal-integrity model Cap
simulation model Cap
footprint 0508
pins: 1, 2

## LLL215R70J474MA11L
designator C?  ValueDisplayed: 0.47µF  (hidden comment: LLL215R70J474MA11L)
CAP, CERM, 0.47 µF, 6.3 V,+/- 20%, X7R, 0508; Manufacturer: MuRata; Polarized: N; CompType: Capacitor; Value: 0.47uF; U/M: EA; Cap_F: 0.00000047; Tolerance_%: 20; VDC_V: 6.3; Value2: 6.3V; TaMin_C: -55; TaMax_C: 125; Cap_Case: 0508; SizeArea_mm2: 2.5; SizeAreaWB_mm2: 6.75; SizeX_mm: 1.25; SizeY_mm: 2; SizeZ_mm: 1; AEC Category: Q200
signal-integrity model Cap
simulation model Cap
footprint 0508
pins: 1, 2

## LLL215R71A224MA11L
designator C?  ValueDisplayed: 0.22µF  (hidden comment: LLL215R71A224MA11L)
CAP, CERM, 0.22 µF, 10 V,+/- 20%, X7R, 0508; Manufacturer: MuRata; Polarized: N; CompType: Capacitor; Value: 0.22uF; U/M: EA; Cap_F: 0.00000022; Tolerance_%: 20; VDC_V: 10; Value2: 10V; TaMin_C: -55; TaMax_C: 125; Cap_Case: 0508; SizeArea_mm2: 2.5; SizeAreaWB_mm2: 6.75; SizeX_mm: 1.25; SizeY_mm: 2; SizeZ_mm: 1; AEC Category: Q200
signal-integrity model Cap
simulation model Cap
footprint 0508
pins: 1, 2

## LLL215R71C104MA11L
designator C?  ValueDisplayed: 0.1µF  (hidden comment: LLL215R71C104MA11L)
CAP, CERM, 0.1 µF, 16 V,+/- 20%, X7R, 0508; Manufacturer: MuRata; Polarized: N; CompType: Capacitor; Value: 0.1uF; U/M: EA; Cap_F: 0.0000001; Tolerance_%: 20; VDC_V: 16; Value2: 16V; TaMin_C: -55; TaMax_C: 125; Cap_Case: 0508; SizeArea_mm2: 2.5; SizeAreaWB_mm2: 6.75; SizeX_mm: 1.25; SizeY_mm: 2; SizeZ_mm: 1; AEC Category: Q200
signal-integrity model Cap
simulation model Cap
footprint 0508
pins: 1, 2

## LLL215R71C473MA11L
designator C?  ValueDisplayed: 0.047µF  (hidden comment: LLL215R71C473MA11L)
CAP, CERM, 0.047 µF, 16 V,+/- 20%, X7R, 0508; Manufacturer: MuRata; Polarized: N; CompType: Capacitor; Value: 0.047uF; U/M: EA; Cap_F: 0.000000047; Tolerance_%: 20; VDC_V: 16; Value2: 16V; TaMin_C: -55; TaMax_C: 125; Cap_Case: 0508; SizeArea_mm2: 2.5; SizeAreaWB_mm2: 6.75; SizeX_mm: 1.25; SizeY_mm: 2; SizeZ_mm: 1; AEC Category: Q200
signal-integrity model Cap
simulation model Cap
footprint 0508
pins: 1, 2

## LLL215R71E223MA11L
designator C?  ValueDisplayed: 0.022µF  (hidden comment: LLL215R71E223MA11L)
CAP, CERM, 0.022 µF, 25 V,+/- 20%, X7R, 0508; Manufacturer: MuRata; Polarized: N; CompType: Capacitor; Value: 0.022uF; U/M: EA; Cap_F: 0.000000022; Tolerance_%: 20; VDC_V: 25; Value2: 25V; TaMin_C: -55; TaMax_C: 125; Cap_Case: 0508; SizeArea_mm2: 2.5; SizeAreaWB_mm2: 6.75; SizeX_mm: 1.25; SizeY_mm: 2; SizeZ_mm: 1; AEC Category: Q200
signal-integrity model Cap
simulation model Cap
footprint 0508
pins: 1, 2

## LLL215R71H103MA11L
designator C?  ValueDisplayed: 0.01µF  (hidden comment: LLL215R71H103MA11L)
CAP, CERM, 0.01 µF, 50 V,+/- 20%, X7R, 0508; Manufacturer: MuRata; Polarized: N; CompType: Capacitor; Value: 0.01uF; U/M: EA; Cap_F: 0.00000001; Tolerance_%: 20; VDC_V: 50; Value2: 50V; TaMin_C: -55; TaMax_C: 125; Cap_Case: 0508; SizeArea_mm2: 2.5; SizeAreaWB_mm2: 6.75; SizeX_mm: 1.25; SizeY_mm: 2; SizeZ_mm: 1; AEC Category: Q200
signal-integrity model Cap
simulation model Cap
footprint 0508
pins: 1, 2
